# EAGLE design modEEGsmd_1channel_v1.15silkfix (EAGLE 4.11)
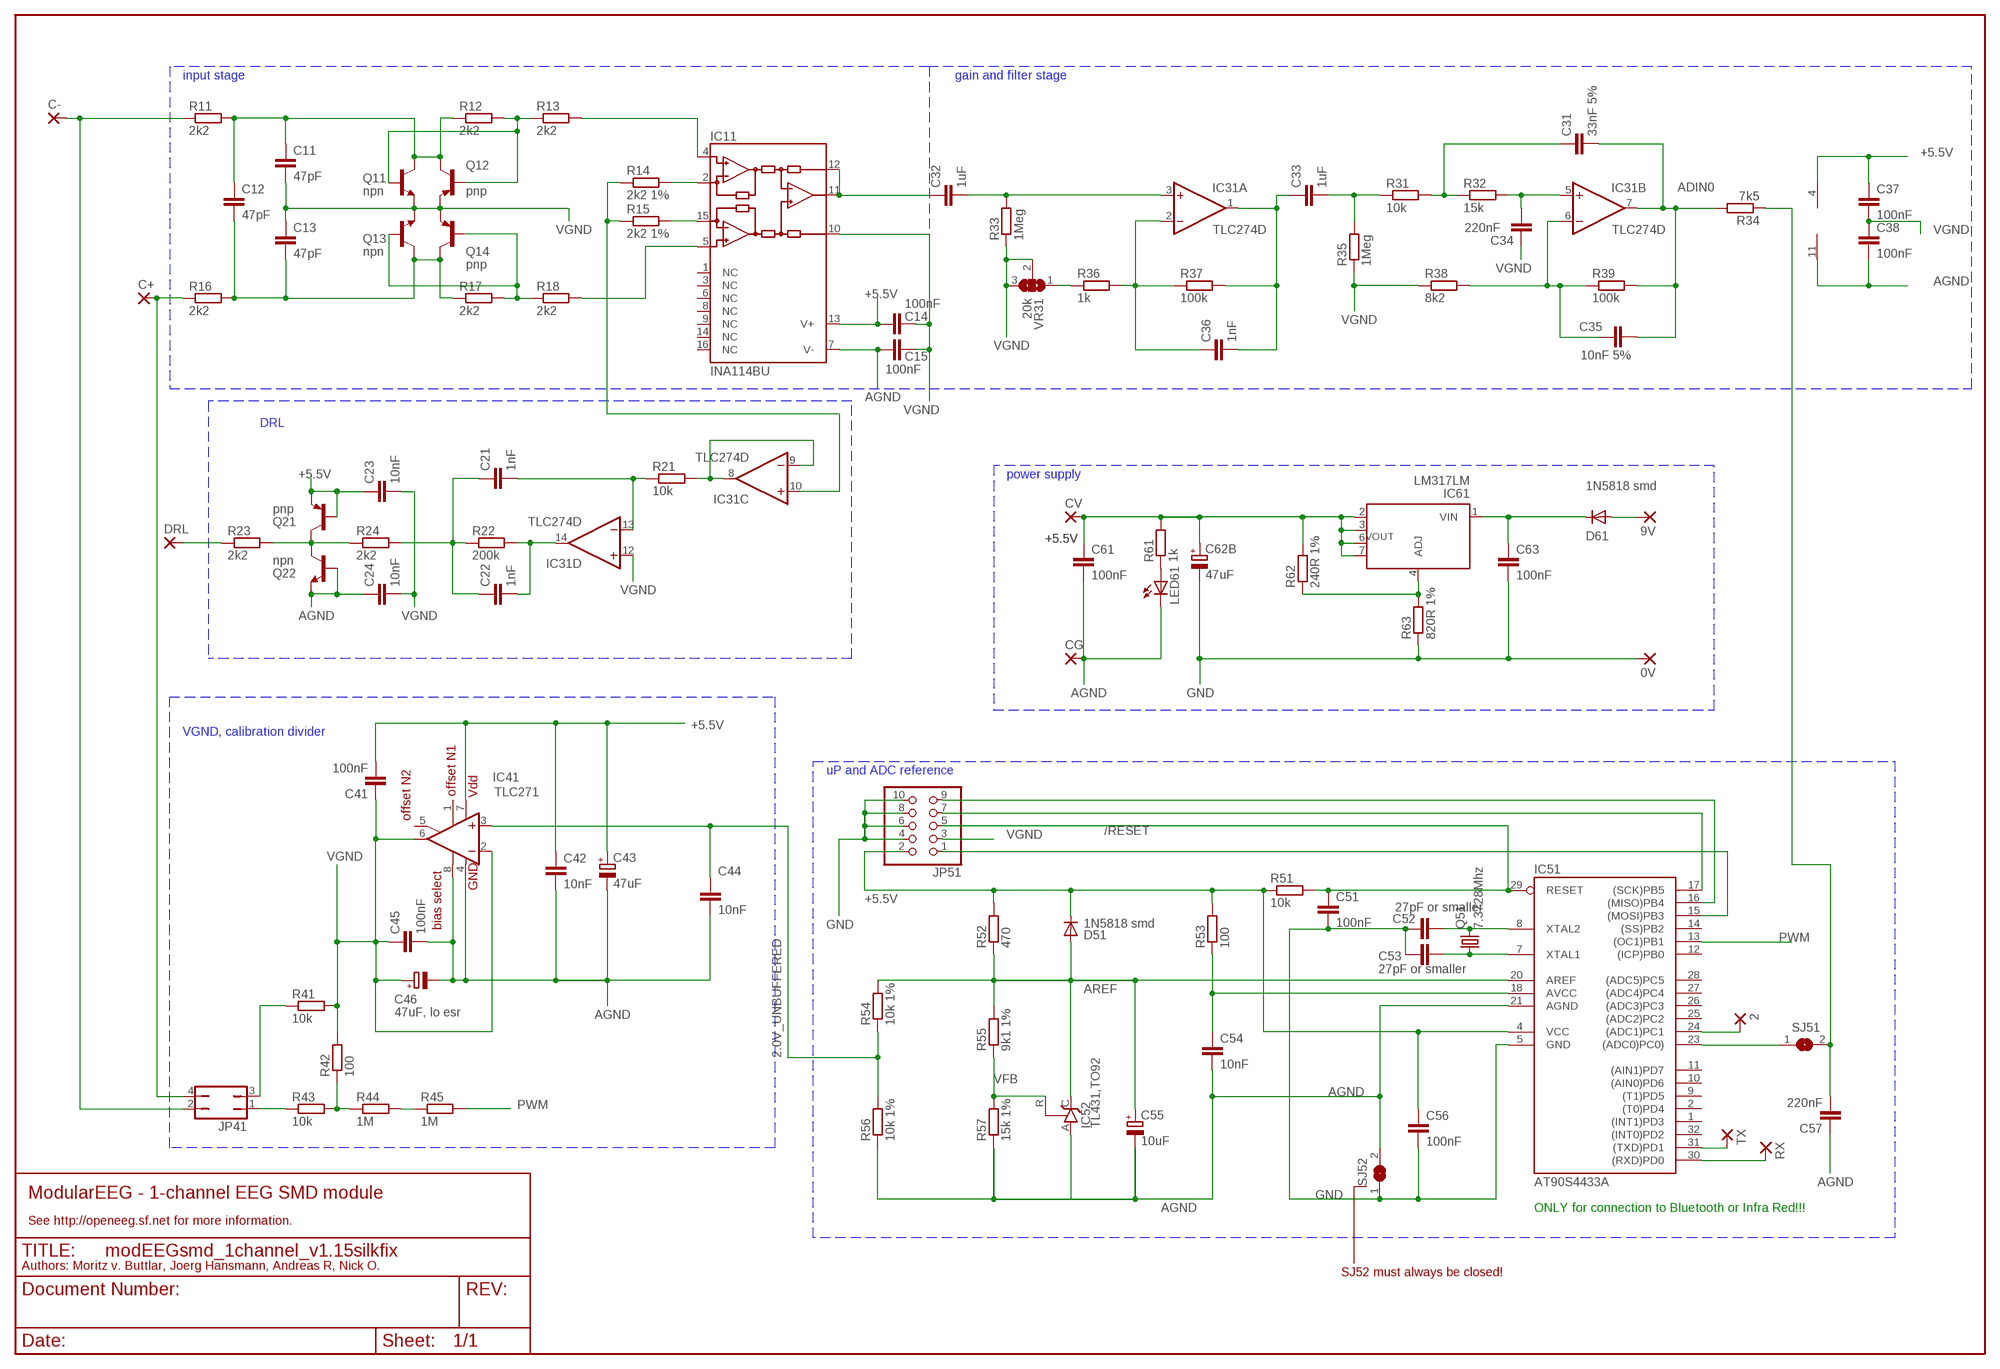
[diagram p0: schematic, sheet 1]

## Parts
0V  1,6/0,8  [1,6/0,8]
2  1,6/0,8  [1,6/0,8]
9V  1,6/0,8  [1,6/0,8]
C11  47pF  C-EUC0603K  [C0603K]
C12  47pF  C-EUC0603K  [C0603K]
C13  47pF  C-EUC0603K  [C0603K]
C14  100nF  C-EUC0603K  [C0603K]
C15  100nF  C-EUC0603K  [C0603K]
C21  1nF  C-EUC0603K  [C0603K]
C22  1nF  C-EUC0603K  [C0603K]
C23  10nF  C-EUC0603K  [C0603K]
C24  10nF  C-EUC0603K  [C0603K]
C31  33nF 5%  C-EUC1206K  [C1206K]
C32  1uF  C-EUC1210K  [C1210K]
C33  1uF  C-EUC1210K  [C1210K]
C34  220nF  C-EU  [C2416]
C35  10nF 5%  C-EUC0805K  [C0805K]
C36  1nF  C-EUC0603K  [C0603K]
C37  100nF  C-EUC0603K  [C0603K]
C38  100nF  C-EUC0603K  [C0603K]
C41  100nF  C-EUC0603K  [C0603K]
C42  10nF  C-EUC0603K  [C0603K]
C43  47uF  CPOL-EUCT3528  [CT3528]
C44  10nF  C-EUC0603K  [C0603K]
C45  100nF  C-EUC0603K  [C0603K]
C46  47uF, lo esr  CPOL-EUCT3528  [CT3528]
C51  100nF  C-EUC0603K  [C0603K]
C52  27pF or smaller  C-EUC0603K  [C0603K]
C53  27pF or smaller  C-EUC0603K  [C0603K]
C54  10nF  C-EUC0603K  [C0603K]
C55  10uF  CPOL-EUCT3216  [CT3216]
C56  100nF  C-EUC0603K  [C0603K]
C57  220nF  C-EU  [C2416]
C61  100nF  C-EUC0603K  [C0603K]
C62B  47uF  CPOL-EUCT3528  [CT3528]
C63  100nF  C-EUC0603K  [C0603K]
C+  1,6/0,8  [1,6/0,8]
C-  1,6/0,8  [1,6/0,8]
CG  1,6/0,8  [1,6/0,8]
CV  1,6/0,8  [1,6/0,8]
D51  1N5818 smd  DIODE-SMB  [SMB]
D61  1N5818 smd  DIODE-SMB  [SMB]
DRL  1,6/0,8  [1,6/0,8]
IC11  INA114BU  INA111U  [SO16-1]
IC31  TLC274D  [SO14]
IC41  TLC271  TLC271D  [SO08]
IC51  AT90S4433A  [TQFP32-08]
IC52  TL431,TO92  TL431CLP  [TO92-CLP]
IC61  LM317LM  [SO08]
JP41  JP2Q  [JP2Q]
JP51  PINHD-2X5  [2X05]
LED61  LEDCHIPLED_0805  [CHIPLED_0805]
Q11  npn  BC847SMD  [SOT23]
Q12  pnp  BC857CSMD  [SOT23-BEC]
Q13  npn  BC847SMD  [SOT23]
Q14  pnp  BC857CSMD  [SOT23-BEC]
Q21  pnp  BC857CSMD  [SOT23-BEC]
Q22  npn  BC847SMD  [SOT23]
Q51  7.3728Mhz  CRYTALHC49S  [HC49/S]
R11  2k2  R-EU_R0805  [R0805]
R12  2k2  R-EU_R0805  [R0805]
R13  2k2  R-EU_R0805  [R0805]
R14  2k2 1%  R-EU_R0805  [R0805]
R15  2k2 1%  R-EU_R0805  [R0805]
R16  2k2  R-EU_R0805  [R0805]
R17  2k2  R-EU_R0805  [R0805]
R18  2k2  R-EU_R0805  [R0805]
R21  10k  R-EU_R0805  [R0805]
R22  200k  R-EU_M0805  [M0805]
R23  2k2  R-EU_R0805  [R0805]
R24  2k2  R-EU_R0805  [R0805]
R31  10k  R-EU_R0805  [R0805]
R32  15k  R-EU_R0805  [R0805]
R33  1Meg  R-EU_R0805  [R0805]
R34  7k5  R-EU_R0805  [R0805]
R35  1Meg  R-EU_R0805  [R0805]
R36  1k  R-EU_R0805  [R0805]
R37  100k  R-EU_R0805  [R0805]
R38  8k2  R-EU_R0805  [R0805]
R39  100k  R-EU_R0805  [R0805]
R41  10k  R-EU_R0805  [R0805]
R42  100  R-EU_R0805  [R0805]
R43  10k  R-EU_R0805  [R0805]
R44  1M  R-EU_R0805  [R0805]
R45  1M  R-EU_R0805  [R0805]
R51  10k  R-EU_R0805  [R0805]
R52  470  R-EU_R0805  [R0805]
R53  100  R-EU_R0805  [R0805]
R54  10k 1%  R-EU_R0805  [R0805]
R55  9k1 1%  R-EU_R0805  [R0805]
R56  10k 1%  R-EU_R0805  [R0805]
R57  15k 1%  R-EU_R0805  [R0805]
R61  1k  R-EU_R0805  [R0805]
R62  240R 1%  R-EU_R0805  [R0805]
R63  820R 1%  R-EU_R0805  [R0805]
RX  1,6/0,8  [1,6/0,8]
SJ51  SJ  [SJ]
SJ52  SJ  [SJ]
TX  1,6/0,8  [1,6/0,8]
VR31  20k  SJ2W  [SJ_2]

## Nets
2.0V_UNBUFFERED: C44.1 IC41.3(+IN) R54.1 R56.2
+5.5V: C14.1 C23.1 C37.1 C41.2 C42.1 C43.+ C56.1 C61.1 C62B.+ CV.1(P) D51.C IC11.13(V+) IC31.4(P:V+) IC41.7(V+) IC51.4(VCC) IC61.2(VOUT) IC61.3(VOUT) IC61.6(VOUT) IC61.7(VOUT) JP51.2 Q21.B Q21.E R51.1 R52.2 R53.2 R61.2 R62.2
/RESET: C51.1 IC51.29(RESET) JP51.5 R51.2
ADC0: IC51.23((ADC0)PC0)) SJ51.1
ADC1: 2.1(P) IC51.24((ADC1)PC1)
ADIN0: C31.2 C35.2 IC31.7(B:OUT) R34.2 R39.2
AGND: C15.1 C24.1 C38.2 C42.2 C43.- C44.2 C45.2 C46.- C54.2 C55.- C57.1 C61.2 CG.1(P) IC11.7(V-) IC31.11(P:V-) IC41.4(V-) IC41.8(OPT) IC51.21(AGND) IC52.A LED61.C Q22.1(B) Q22.2(E) R56.1 R57.1 SJ52.2
AREF: C55.+ D51.A IC51.20(AREF) IC52.C R52.1 R54.2 R55.2
AVCC: C54.1 IC51.18(AVCC) R53.1
DRL: DRL.1(P) R23.1
GND: 0V.1(P) C51.2 C52.1 C53.1 C56.2 C62B.- C63.2 IC51.5(GND) JP51.4 JP51.6 JP51.8 JP51.10 R63.1 SJ52.1
N$1: IC11.2(RG) R14.2
N$2: IC11.15(RG) R15.2
N$3: IC31.10(C:+IN) R14.1 R15.1
N$4: C32.1 IC11.11(OUT) IC11.12(FB)
N$5: IC11.4(-IN) R13.2
N$6: R36.1 VR31.1
N$7: IC11.5(+IN) R18.2
N$8: C57.2 R34.1 SJ51.2
N$9: C11.1 C12.1 Q11.3(C) Q12.C R11.2 R12.1
N$10: Q13.1(B) Q14.B R17.2 R18.1
N$11: R44.2 R45.1
N$12: C52.2 IC51.8(XTAL2) Q51.2
N$13: C12.2 C13.2 Q13.3(C) Q14.C R16.2 R17.1
N$14: Q11.1(B) Q12.B R12.2 R13.1
N$15: C-.1(P) JP41.2 R11.1
N$16: C+.1(P) JP41.4 R16.1
N$17: C32.2 IC31.3(A:+IN) R33.2
N$18: C36.1 IC31.2(A:-IN) R36.2 R37.1
N$19: C53.2 IC51.7(XTAL1) Q51.1
N$20: Q21.C Q22.3(C) R23.2 R24.1
N$22: C33.1 C36.2 IC31.1(A:OUT) R37.2
N$23: C33.2 R31.1 R35.2
N$24: C35.1 IC31.6(B:-IN) R38.2 R39.1
N$25: IC61.4(ADJ) R62.1 R63.2
N$27: IC51.17((SCK)PB5) JP51.7
N$30: JP41.3 R41.1
N$33: C22.2 IC31.14(D:OUT) R22.2
N$34: R42.1 R43.2 R44.1
N$38: C63.1 D61.C IC61.1(VIN)
N$39: LED61.A R61.1
N$40: 9V.1(P) D61.A
N$41: C21.2 IC31.13(D:-IN) R21.1
N$42: IC51.16((MISO)PB4) JP51.9
N$43: IC51.15((MOSI)PB3) JP51.1
N$45: IC31.8(C:OUT) IC31.9(C:-IN) R21.2
N$48: JP41.1 R43.1
N$53: C31.1 R31.2 R32.1
N$54: C34.2 IC31.5(B:+IN) R32.2
PWM: IC51.13((OC1)PB1) R45.2
RLEG: C21.1 C22.1 R22.1 R24.2
RX: IC51.30((RXD)PD0) RX.1(P)
TX: IC51.31((TXD)PD1) TX.1(P)
VFB: IC52.R R55.1 R57.2
VGND: C11.2 C13.1 C14.2 C15.2 C23.2 C24.2 C34.1 C37.2 C38.1 C41.1 C45.1 C46.+ IC11.10(REF) IC31.12(D:+IN) IC41.2(-IN) IC41.6(OUT) JP51.3 Q11.2(E) Q12.E Q13.2(E) Q14.E R33.1 R35.1 R38.1 R41.2 R42.2 VR31.2 VR31.3
Unconnected: IC11.1(NC) IC11.3(NC) IC11.6(NC) IC11.8(NC) IC11.9(NC) IC11.14(NC) IC11.16(NC) IC41.1(ON1) IC41.5(ON2) IC51.1((INT1)PD3) IC51.2((T0)PD4) IC51.9((T1)PD5) IC51.10((AIN0)PD6) IC51.11((AIN1)PD7) IC51.12((ICP)PB0) IC51.14((SS)PB2) IC51.25((ADC2)PC2) IC51.26((ADC3)PC3) IC51.27((ADC4)PC4) IC51.28((ADC5)PC5) IC51.32((INT0)PD2)

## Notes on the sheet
- input stage | gain and filter stage
- DRL
- power supply
- VGND, calibration divider
- uP and ADC reference
- offset N1 | Vdd
- offset N2
- GND
- bias select
- ModularEEG - 1-channel EEG SMD module
- ONLY for connection to Bluetooth or Infra Red!!!
- See http://openeeg.sf.net for more information.
- Authors: Moritz v. Buttlar, Joerg Hansmann, Andreas R, Nick O.
- SJ52 must always be closed!

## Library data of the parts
0V 2 9V C+ C- CG CV DRL RX TX = WIREPAD:1,6/0,8: THROUGH-HOLE PAD
C11-C15 C21-C24 C31-C38 C41 C42 C44 C45 C51-C54 C56 C57 C61 C63 = rcl:C-EU: CAPACITOR, European symbol
C43 C46 C55 C62B = rcl:CPOL-EU: POLARIZED CAPACITOR, European symbol
D51 D61 = diode:DIODE-: DIODE
IC11 = burr-brown:INA111U: Precision Instrumentation Amplifier
IC31 = linear:TLC274: OP AMP
IC41 = linear:TLC271: OP AMP
IC51 = atmel:AT90S4433: MICROCONTROLLER 4 Kbytes FLASH 128 bytes SRAM 256 bytes EEPROM UART 6-channel 10 bit ADC
IC52 = v-reg:TL431CLP: VOLTAGE REGULATOR
IC61 = linear:LM317LM
JP41 = jumper:JP2Q: JUMPER
JP51 = pinhead:PINHD-2X5: PIN HEADER
LED61 = led:LED: LED
Q11 Q13 Q22 = transistor-npn:BC847*: NPN Transistor
Q12 Q14 Q21 = transistor-pnp:BC857*: PNP Transistror
Q51 = crystal:CRYTAL: CRYSTAL
R11-R18 R21-R24 R31-R39 R41-R45 R51-R57 R61-R63 = rcl:R-EU_: RESISTOR, European symbol
SJ51 SJ52 = jumper:SJ: SMD solder JUMPER
VR31 = jumper:SJ2W: SMD solder JUMPER

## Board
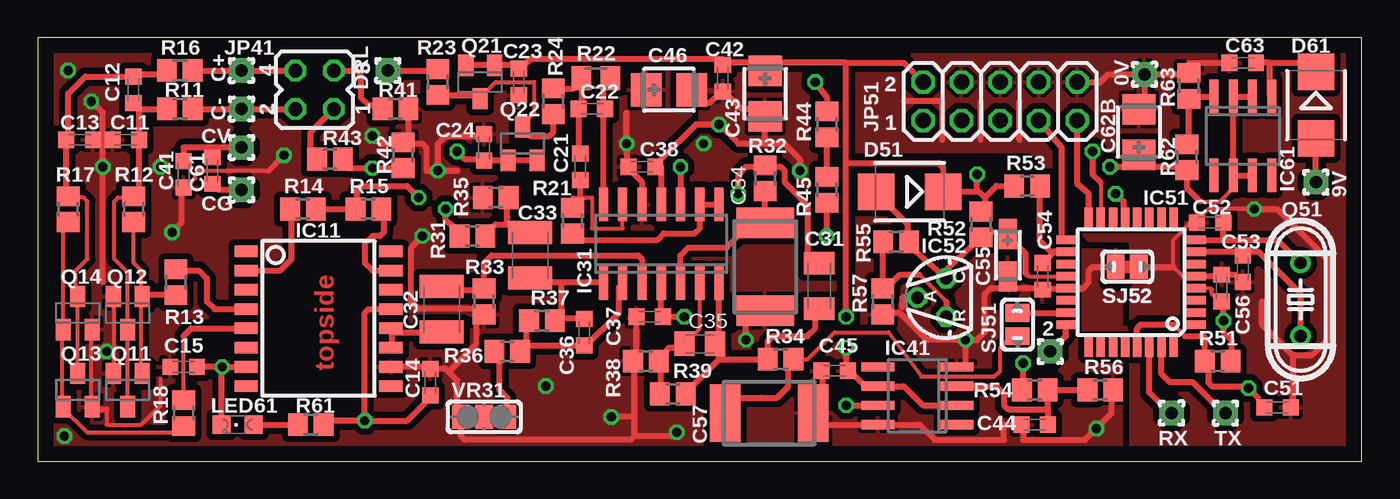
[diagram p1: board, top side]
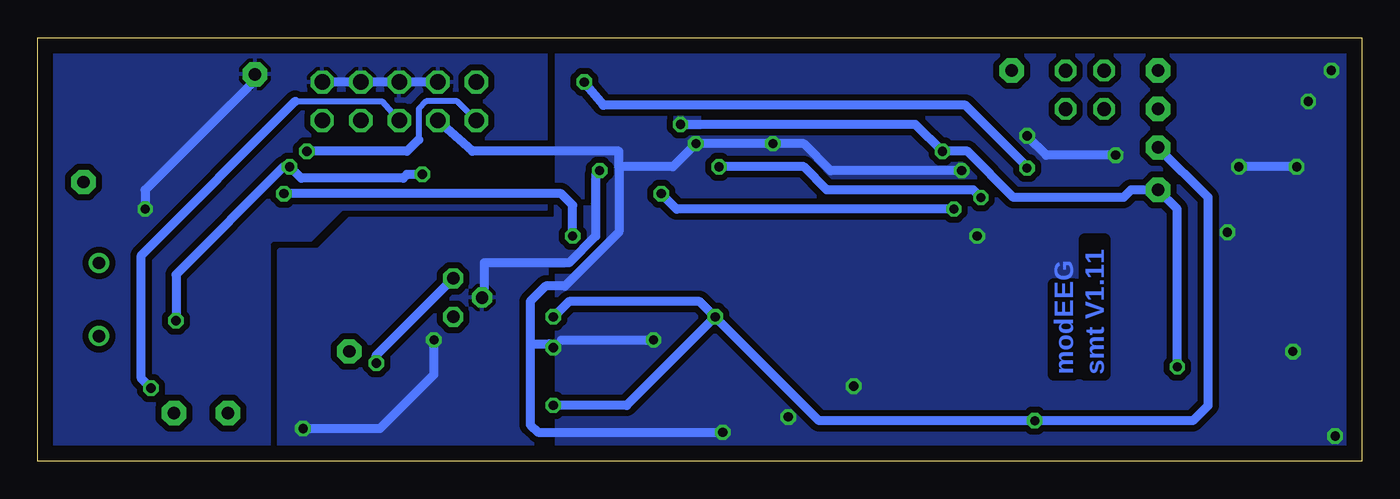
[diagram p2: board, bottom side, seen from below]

Size 87.3 x 27.93 mm. Coordinates in mm from the lower left corner, seen from the top.
Outline: 0,0 87.3,0 87.3,27.93 0,27.93 0,0
Copper layers (1*16): Top 0.035mm / dielectric 1.5mm / Bottom 0.035mm
Design rules "OLIMEX_8mils": minimum track width 10mil, minimum drill 24mil, track to track 8mil, track to pad 8mil, pad to pad 8mil, via to via 8mil, smd to smd 8mil, copper to edge 40mil, drill to drill 10mil, minimum pad ring 10mil, minimum via ring 8mil, stop-mask expansion 0mil, vias tented up to drill 0mil, thermal gap 10mil
tRestrict: 6 lines

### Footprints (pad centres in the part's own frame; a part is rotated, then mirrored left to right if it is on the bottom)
1,6/0,8 = drill 0.813 pad 1.6 octagon: 1 0,0
C0603K = smd 1.05 x 1.08: 1 -0.875,0; 2 0.875,0
C1206K = smd 1.5 x 2: 1 -1.5,0; 2 1.5,0
C1210K = smd 1.5 x 2.9: 1 -1.5,0; 2 1.5,0
C2416 = smd 2 x 3.8: 1 -2.9,0; 2 2.9,0
C0805K = smd 1.3 x 1.6: 1 -1,0; 2 1,0
CT3528 = smd 2 x 2.2: + 1.5,0; - -1.5,0
CT3216 = smd 2 x 1.2: + 1.4,0; - -1.4,0
SMB = smd 2.4 x 2.4: A 2.2,0; C -2.2,0
SO16-1 = smd 0.762 x 1.524: 1 -4.445,-4.775; 2 -3.175,-4.775; 3 -1.905,-4.775; 4 -0.635,-4.775; 5 0.635,-4.775; 6 1.905,-4.775; 7 3.175,-4.775; 8 4.445,-4.775; 9 4.445,4.775; 10 3.175,4.775; 11 1.905,4.775; 12 0.635,4.775; 13 -0.635,4.775; 14 -1.905,4.775; 15 -3.175,4.775; 16 -4.445,4.775
SO14 = smd 0.6 x 2.2: 1 -3.81,-2.6; 2 -2.54,-2.6; 3 -1.27,-2.6; 4 0,-2.6; 5 1.27,-2.6; 6 2.54,-2.6; 7 3.81,-2.6; 8 3.81,2.6; 9 2.54,2.6; 10 1.27,2.6; 11 0,2.6; 12 -1.27,2.6; 13 -2.54,2.6; 14 -3.81,2.6
SO08 = smd 0.6 x 2.2: 1 -1.905,-2.6; 2 -0.635,-2.6; 3 0.635,-2.6; 4 1.905,-2.6; 5 1.905,2.6; 6 0.635,2.6; 7 -0.635,2.6; 8 -1.905,2.6
TQFP32-08 = smd 1.27 x 0.559: 1 -4.293,2.8; 2 -4.293,2; 3 -4.293,1.2; 4 -4.293,0.4; 5 -4.293,-0.4; 6 -4.293,-1.2; 7 -4.293,-2; 8 -4.293,-2.8; 17 4.293,-2.8; 18 4.293,-2; 19 4.293,-1.2; 20 4.293,-0.4; 21 4.293,0.4; 22 4.293,1.2; 23 4.293,2; 24 4.293,2.8 | smd 0.559 x 1.27: 9 -2.8,-4.293; 10 -2,-4.293; 11 -1.2,-4.293; 12 -0.4,-4.293; 13 0.4,-4.293; 14 1.2,-4.293; 15 2,-4.293; 16 2.8,-4.293; 25 2.8,4.293; 26 2,4.293; 27 1.2,4.293; 28 0.4,4.293; 29 -0.4,4.293; 30 -1.2,4.293; 31 -2,4.293; 32 -2.8,4.293
TO92-CLP = drill 0.813 octagon: A 0,1.905; C 1.27,0; R -1.27,0
JP2Q = drill 0.914 pad 1.422 octagon: 1 -1.27,-1.27; 2 -1.27,1.27; 3 1.27,-1.27; 4 1.27,1.27
2X05 = drill 1.016 pad 1.524 octagon: 1 -5.08,-1.27; 2 -5.08,1.27; 3 -2.54,-1.27; 4 -2.54,1.27; 5 0,-1.27; 6 0,1.27; 7 2.54,-1.27; 8 2.54,1.27; 9 5.08,-1.27; 10 5.08,1.27
CHIPLED_0805 = smd 1.2 x 1.2: A 0,-1.05; C 0,1.05
SOT23 = smd 1 x 1.4: 1 -0.95,-1.1; 2 0.95,-1.1; 3 0,1.1
SOT23-BEC = smd 1 x 1.4: B -0.95,-1.1; C 0,1.1; E 0.95,-1.1
HC49/S = drill 0.813 round: 1 -2.413,0; 2 2.413,0
R0805 = smd 1.3 x 1.5: 1 -0.85,0; 2 0.85,0
M0805 = smd 1.3 x 1.6: 1 -0.95,0; 2 0.95,0
SJ = smd 1.168 x 1.6: 1 -0.762,0; 2 0.762,0
SJ_2 = smd 1.168 x 1.6: 1 -1.524,0; 2 0,0; 3 1.524,0

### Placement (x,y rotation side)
0V  72.99,25.52 270 top
2  66.76,7.23 90 top
9V  84.29,18.41 270 top
C11  5.8,21.2 180 top
C12  6.31,24.51 90 top
C13  2.76,21.2 180 top
C14  25.87,5.2 90 top
C15  9.61,6.22 180 top
C21  35.78,19.43 270 top
C22  36.54,23.24 0 top
C23  31.71,25.01 270 top
C24  29.43,20.7 90 top
C31  51.52,11.55 270 top
C32  26.63,10.03 90 top
C33  32.47,13.58 90 top
C34  47.97,12.82 90 top
C35  43.65,7.74 0 top
C36  36.03,8.5 90 top
C37  40.35,9.52 180 top
C38  39.84,19.43 0 top
C41  9.61,18.92 90 top
C42  45.17,25.27 270 top
C43  47.97,24.25 90 top
C44  65.75,2.41 180 top
C45  52.54,5.96 180 top
C46  41.62,24.51 180 top
C51  81.75,3.55 0 top
C52  77.31,15.74 0 top
C53  79.46,12.7 90 top
C54  66.26,12.19 270 top
C55  63.97,13.58 90 top
C56  78.07,11.43 90 top
C57  48.22,3.17 180 top
C61  11.52,19.17 270 top
C62B  72.61,21.71 270 top
C63  79.46,26.28 180 top
C+  13.42,25.78 90 top
C-  13.42,23.24 90 top
CG  13.42,17.9 90 top
CV  13.42,20.7 90 top
D51  57.49,17.77 180 top
D61  84.29,23.49 270 top
DRL  23.08,25.78 90 top
IC11  18.5,9.39 270 top
IC31  41.11,14.35 0 top
IC41  58,4.31 90 top
IC51  72.1,11.81 180 top
IC52  59.91,10.79 90 top
IC61  79.46,21.46 180 top
JP41  18.25,24.51 90 top
JP51  63.46,23.74 0 top
LED61  13.17,2.41 90 top
Q11  5.93,4.69 180 top
Q12  5.93,9.77 180 top
Q13  2.63,4.69 0 top
Q14  2.63,9.77 0 top
Q21  29.17,25.01 180 top
Q22  31.97,20.95 0 top
Q51  83.27,10.66 90 top
R11  9.36,23.24 180 top
R12  6.31,16.63 270 top
R13  9.11,11.81 90 top
R14  17.49,16.63 180 top
R15  21.81,16.63 0 top
R16  9.36,25.78 180 top
R17  1.99,16.63 270 top
R18  9.61,3.17 90 top
R21  35.27,15.87 270 top
R22  36.79,25.27 0 top
R23  26.38,25.01 270 top
R24  34,23.74 90 top
R31  28.66,14.85 180 top
R32  47.97,18.66 270 top
R33  29.43,10.54 90 top
R34  48.98,6.73 180 top
R35  30.19,17.39 0 top
R36  30.95,7.23 0 top
R37  33.24,9.27 0 top
R38  40.09,6.6 0 top
R39  41.87,4.44 0 top
R41  23.58,23.24 0 top
R42  24.09,20.19 90 top
R43  19.27,19.93 0 top
R44  52.03,22.22 270 top
R45  52.03,17.9 270 top
R51  77.81,6.6 180 top
R52  62.19,15.62 90 top
R53  65.24,18.16 180 top
R54  65.75,4.69 180 top
R55  56.6,14.47 0 top
R56  70.07,4.69 180 top
R57  55.72,10.54 90 top
R61  18,2.41 0 top
R62  75.78,20.06 270 top
R63  75.91,24.76 270 top
RX  74.77,3.17 270 top
SJ51  64.61,9.01 270 top
SJ52  71.84,12.82 180 top
TX  78.32,3.17 180 top
VR31  29.43,2.92 180 top

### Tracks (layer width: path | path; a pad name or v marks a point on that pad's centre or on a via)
2.0V_UNBUFFERED
  Top 0.254: C44.1 66.62,2.55 66.51,2.66 66.6,2.75
  Top 0.406: 66.6,3.42 66.6,2.75 | 66.6,3.42 R54.1 R56.2 | IC41.3 63.21,4.95 63.72,4.44 63.72,3.68 63.97,3.42 66.6,3.42
+5.5V  (via drill 0.61)
  Top 0.254: 41.11,9.63 C37.1 41.11,9.52 | 47.97,26.28 C43.+ | 45.17,26.28 45.17,26.26 45.2,26.26 45.17,26.28 | R61.2 19.01,2.41 19.27,2.66 | 25.87,4.19 C14.1 | IC51.4 77.32,11.41 77.43,11.3 77.43,11.04 77.94,10.54 77.95,10.55 C56.1 78.18,10.55 78.19,10.54 | 72.86,19.55 72.86,19.43 72.61,19.68 C62B.+ | IC61.3 78.9,24.06 78.96,24 79.02,24.06 | 78.83,19.04 78.96,18.92 78.9,18.86 IC61.6 78.76,18.86 78.7,18.92 78.7,17.9 77.94,17.14 76.67,17.14 | IC61.7 80.03,18.86 79.97,18.92 79.91,18.86 | R62.2 75.69,19.21 75.65,19.17 75.4,19.43 | 62.45,16.89 R52.2 | 61.94,17.77 62.07,17.77 | 78.7,6.73 78.66,6.69 R51.1 | R53.2 64.48,18.16 | C61.1 11.39,20.17 11.39,20.44 11.14,20.7 | 30.12,26.1 30.19,26.03 | Q21.B 30.12,26.1 | 30.12,26.1 30.1,26.11 | C23.1 31.71,25.78 31.63,25.86 | 31.82,25.89 C23.1 | 45.17,26.28 C42.1 | 45.17,26.28 45.17,26.54 | C23.1 31.71,26.03 31.63,26.11
  Top 0.406: 41.11,9.63 IC31.4 | 45.17,26.28 47.97,26.28 53.3,26.28 | v21.55,2.66 19.27,2.66 | v21.55,2.66 24.35,2.66 25.87,4.19 | IC11.13 21.81,10.03 21.55,9.77 v21.55,2.66 | v42.63,9.52 C37.1 | v70.7,19.43 72.86,19.43 75.4,19.43 | 79.02,24.06 IC61.2 | 78.83,19.04 IC61.3 | IC61.6 79.91,18.86 | R62.2 75.78,18.03 76.67,17.14 | 53.3,26.28 57.11,26.28 JP51.2 | 62.07,17.77 62.45,17.39 | 62.45,17.39 62.45,16.89 | 78.19,10.54 v78.19,9.27 78.19,8.5 78.7,8 78.7,6.73 | v53.3,3.68 IC41.7 | v53.3,9.52 53.3,19.68 | 53.3,19.68 53.3,26.28 | 62.45,17.39 63.21,18.16 R53.2 | v61.94,18.92 61.94,17.77 D51.C 59.69,19.38 59.4,19.68 53.3,19.68 | CV.1 11.14,20.7 9.61,20.7 C41.2 | 30.1,26.11 Q21.E | 31.82,25.89 32.47,26.54 45.17,26.54 | 31.63,26.11 Q21.B
  Bottom 0.61: CV.1 10.12,17.39 10.12,3.68 11.14,2.66 v21.55,2.66 35.78,2.66 v42.63,9.52 | v78.19,9.27 78.19,12.31 71.08,19.43 v70.7,19.43 69.94,18.66 63.21,18.66 62.95,18.92 v61.94,18.92 | v42.63,9.52 48.48,3.68 v53.3,3.68 | v42.63,9.52 43.65,10.54 52.29,10.54 v53.3,9.52
/RESET  (via drill 0.61)
  Top 0.254: IC51.29 72.5,7.49 72.48,7.49 | 72.73,9.01 72.75,9.01 | 76.96,6.69 R51.2 77.18,6.38 | 74.89,9.01 75.65,8.25 | C51.1 80.75,3.42 80.48,3.42 80.48,4.19 | 79.72,4.95 v79.84,4.82
  Top 0.406: IC51.29 72.48,8.76 72.73,9.01 | 72.75,9.01 74.89,9.01 | 77.18,6.38 77.18,5.2 77.43,4.95 79.72,4.95 | v79.84,4.82 80.48,4.19 | R51.2 76.92,6.6 76.92,8.25 75.65,8.25
  Bottom 0.406: JP51.5 64.61,23.74 70.32,23.74
  Bottom 0.61: 70.32,23.74 80.48,13.58 80.48,5.46 v79.84,4.82
ADC0
  Top 0.254: 67.78,9.77 IC51.23
  Top 0.406: SJ51.1 67.78,9.77
ADC1
  Top 0.406: IC51.24 67.81,8.28 2.1
ADIN0
  Top 0.254: 42.38,4.02 R39.2 42.63,4.44 | R34.2 48.22,6.73 | 44.41,7.74 C35.2 44.92,7.74
  Top 0.406: IC31.7 44.92,7.74 44.92,6.73 | 42.63,4.44 44.92,6.73 | 44.92,6.73 45.17,6.73 | 45.17,6.73 R34.2 48.13,7.91 48.48,8.25 50.76,8.25 51.27,8.76 51.27,10.03 51.29,10.05 C31.2 | 45.17,6.73 45.17,7.23
AGND  (via drill 0.61)
  Top 0.254: 55.8,9.77 R57.1 | C15.1 10.38,6.22 | 45.29,24.39 C42.2 45.17,24.51 | IC41.4 61.18,6.22 61.43,6.22 | 11.91,17.9 C61.2 | 12.12,6.18 v12.15,6.22 | 51.78,5.96 C45.2 | 51.78,2.41 51.78,3.17 C57.1 | 70.83,4.69 R56.1 | 66.13,11.43 C54.2 | C54.2 | C54.2 66.36,11.41 | 62.83,11.43 63.84,11.43 63.97,11.55 C55.- 63.97,12.31 | C46.- 43.14,24.51 44.02,23.63 | 41.11,19.93 41.11,19.43 C38.2 40.6,19.43 | 31.02,19.87 30.95,19.93 | Q22.1 31.02,19.87 | 31.02,19.87 31.03,19.85 | C24.1 29.43,19.93 29.51,19.85 | C43.- 47.97,23.24 47.97,22.73 C43.-
  Top 0.406: v61.18,8 58.64,8 56.86,9.77 55.8,9.77 | C15.1 v12.15,6.22 IC11.7 | 47.97,20.95 47.97,22.73 | 45.29,24.39 46.44,23.24 47.97,23.24 | 47.97,20.95 46.19,20.95 v44.92,22.22 43.4,22.22 41.11,19.93 | 70.83,4.69 70.83,3.17 v69.81,2.15 69.05,1.39 64.99,1.39 64.99,2.41 C44.2 63.72,2.41 63.72,1.39 59.14,1.39 58.13,2.41 IC41.8 51.78,2.41 | v61.18,8 61.18,6.22 | CG.1 11.91,17.9 | LED61.C 12.12,6.18 | 51.78,3.17 51.78,5.96 | 66.13,11.43 62.83,11.43 62.45,11.04 62.45,8.5 61.94,8 v61.18,8 | 66.36,11.41 IC51.21 68.9,11.41 69.3,11.81 69.3,12.57 69.56,12.82 SJ52.2 | v50.25,19.17 50.25,19.93 49.24,20.95 47.97,20.95 | 41.11,19.43 IC31.11 | 31.03,19.85 Q22.2 | 29.51,19.85 Q22.1 | 29.43,19.93 28.16,19.93 v27.65,20.44 | 44.02,23.63 44.3,23.63 45.17,24.51 | IC52.A 56.99,10.79 56.99,10.16
  Bottom 0.254: v50.25,19.17 50.51,18.92
  Bottom 0.61: v44.92,22.22 29.43,22.22 v27.65,20.44 26,20.44 22.95,17.39 15.71,17.39 15.2,17.9 CG.1 12.15,16.63 v12.15,6.22 | v69.81,2.15 64.73,2.15 61.18,5.71 v61.18,8 | 50.51,18.92 50.51,14.85 52.29,13.08 57.87,13.08 57.87,10.79 IC52.A
  pour Top (isolate 0.406, rank 2): 43.65,35.68 75.65,35.68 75.65,-6.23 43.65,-6.23
  pour Bottom (isolate 0.406, rank 2): 43.65,35.68 75.65,35.68 75.65,-6.23 43.65,-6.23
AREF  (via drill 0.61)
  Top 0.254: IC51.20 67.81,12.19 65.37,12.19 65.24,12.31 | 55.29,17.69 D51.A | 57.37,14.56 R55.2 57.58,14.35 57.62,14.35 57.62,14.09 | R52.1 62.45,15.11 | R54.2 64.99,4.69 | 63.97,15.11 C55.+
  Top 0.406: 55.29,17.69 57.37,15.62 57.37,14.56 | R52.1 59.91,12.61 IC52.C 57.62,14.09 | 62.45,15.11 63.97,15.11 63.97,14.85 65.11,13.71 65.11,12.44 65.24,12.31 | 64.99,4.69 v64.99,6.47
  Bottom 0.61: v64.99,6.47 64.99,6.98 IC52.C
AVCC
  Top 0.254: R53.1 66,18.16 | 66.26,13.08 C54.1
  Top 0.406: 66.89,13.71 67.02,13.84 67.78,13.84 IC51.18 | 66.89,13.71 66.26,13.08 | R53.1 66.09,14.51 66.89,13.71
DRL
  Top 0.254: 26.38,25.78 R23.1
  Top 0.406: DRL.1 26.38,25.78
GND  (via drill 0.61)
  Top 0.254: 78.18,12.3 78.19,12.31 | 78.18,12.3 C56.2 78.05,12.31 77.94,12.31 | 78.09,12.21 78.18,12.3 | 78.97,12.31 C53.1 79.46,11.81 | IC51.5 75.51,12.21 74.89,12.82 74.89,14.6 76.42,16.12 76.43,16.11 C52.1 | R63.1 75.91,25.52 | R63.1 75.91,26.28 | 75.82,25.52 R63.1 | v80.23,16.63 77.18,16.63 76.42,15.87 | 82.75,3.68 82.77,3.68 82.62,3.54 | 82.62,3.54 82.51,3.42 | 82.62,3.54 C51.2 | C62B.- 72.61,23.24 72.99,22.85 72.99,22.35
  Top 0.406: IC51.5 78.09,12.21 | 78.05,12.31 78.97,12.31 | SJ52.1 74.89,12.82 | 75.91,26.28 C63.2 | 0V.1 75.82,25.52 | 0V.1 70.57,25.52 70.33,25.28 70.08,25.01 JP51.10 | 0V.1 72.99,22.85 | 80.73,10.54 80.73,9.01 82.77,6.98 | 82.77,6.98 84.04,6.98 85.05,8 85.05,13.33 81.75,16.63 v80.23,16.63 | 82.77,6.98 82.77,3.68 | 57.11,23.74 59.65,23.74 59.65,21.2 | 62.19,21.2 62.19,23.74 | 64.73,21.2 64.73,23.74
  Top 0.813: 70.83,12.82 SJ52.1
  Bottom 0.254: 0V.1 72.99,25.14
  Bottom 0.61: 72.99,25.14 80.23,17.9 v80.23,16.63 | JP51.10 JP51.8 JP51.6 JP51.4
  pour Top (isolate 0.406): 53.81,32.63 53.81,20.44 65.49,20.44 68.03,17.9 68.03,15.87 69.3,14.6 71.84,14.6 72.1,14.35 72.1,-2.93 89.88,-2.93 89.88,32.63
  pour Bottom (isolate 0.406): 53.81,32.63 53.81,16.63 67.27,16.63 69.3,14.6 71.84,14.6 72.1,14.35 72.1,-2.93 89.88,-2.93 89.88,32.63
N$1
  Top 0.254: 16.73,16.63 R14.2
  Top 0.406: IC11.2 15.96,12.57 16.73,13.33 16.73,16.63
N$2
  Top 0.254: 22.57,16.63 R15.2 22.82,16.63
  Top 0.406: IC11.15 22.06,12.57 21.55,13.08 21.55,14.35 22.06,14.85 22.57,14.85 22.82,15.11 22.82,16.63
N$3  (via drill 0.61)
  Top 0.254: R14.1 18.25,16.63 | R15.1 21.04,16.72
  Top 0.406: R14.1 R15.1 | 21.04,16.72 21.04,17.9 21.3,18.16 24.35,18.16 v25.11,17.39 | v42.38,19.43 IC31.10
  Bottom 0.61: v42.38,19.43 36.79,19.43 35.27,17.9 25.62,17.9 v25.11,17.39
N$4
  Top 0.254: 23.33,8.76 IC11.12 23.53,8.5 | 23.33,7.54 IC11.11 | 26.35,8.5 C32.1
  Top 0.406: 23.33,8.76 23.33,7.54 | 23.53,8.5 26.35,8.5
N$5
  Top 0.254: R13.2 9.11,12.57
  Top 0.406: IC11.4 11.65,10.03 11.14,10.54 11.14,12.06 10.63,12.57 9.11,12.57
N$6
  Top 0.254: 30.44,6.89 R36.1
  Top 0.406: 30.44,6.89 30.44,4.69 30.95,4.19 VR31.1
N$7
  Top 0.254: R18.2 9.61,8.25
  Top 0.406: 9.61,8.25 10.12,8.76 IC11.5
N$8
  Top 0.254: 49.49,5.96 49.58,6.31 49.83,6.31 R34.1 50.76,6.73 52.54,8.5 56.1,8.5 58.26,5.58 63.08,5.58 63.46,5.96 63.46,7.49 64.22,8.25 SJ51.2 | C57.2 45.17,3.17 45.17,4.19
  Top 0.406: 49.49,5.96 49.49,4.95 48.73,4.19 47.71,4.19 45.17,4.19
N$9
  Top 0.254: 5.93,3.42 Q11.3 Q12.C 5.93,12.44 5.04,13.33 5.04,17.14 5.3,17.39 5.55,17.39 6.31,17.65 | 6.31,23.74 6.82,23.24 | 6.31,23.74 C12.1 | 6.68,23.38 6.31,23.74 | 6.31,17.65 6.68,18.01 | 6.31,17.65 R12.1
  Top 0.406: 6.82,23.24 R11.2 | 6.68,23.38 C11.1 6.68,18.01
N$10
  Top 0.254: R18.1 9.96,1.9 3.26,1.9 1.49,3.65 | 1.49,3.65 1.74,3.68 | 1.49,3.65 Q13.1 1.61,3.66 1.61,8.63 1.64,8.63 Q14.B 1.68,15.55 1.99,15.87 R17.2
N$11
  Top 0.254: R45.1 52.03,18.66
  Top 0.406: R45.1 R44.2
N$12
  Top 0.254: Q51.2 83.15,13.08 | IC51.8
  Top 0.406: 78.19,14.6 81.75,14.6 Q51.2 | 78.19,14.6 C52.2 | IC51.8 78.19,14.6
N$13
  Top 0.254: Q13.3 Q14.C 2.63,11.04 2.5,11.17 2.5,12.57 3.26,13.33 3.26,17.14 3.01,17.39 1.99,17.39 | C12.2 6.31,25.52 | 8.26,25.52 R16.2 | C13.2 1.99,21.2 | 1.99,17.39 1.88,17.51 | 2.25,17.65 2.08,17.48 R17.1 1.99,17.39
  Top 0.406: 6.31,25.52 8.26,25.52 | C12.2 3.12,25.38 1.99,24.25 1.99,21.2 | 1.88,17.51 C13.2
N$14
  Top 0.254: 6.82,5.73 6.82,5.71 | Q11.1 6.82,5.73 | 6.82,5.73 6.82,10.81 Q12.B 6.88,10.98 6.82,11.04 6.82,12.57 6.31,13.08 R12.2 6.31,15.87 | R13.1 9.11,11.04 9.04,10.98
  Top 0.406: 6.88,10.98 9.04,10.98
N$15
  Top 0.406: JP41.2 C-.1 R11.1
N$16
  Top 0.406: JP41.4 C+.1 R16.1
N$17
  Top 0.254: 29.43,11.3 R33.2 | C32.2 26.61,11.3
  Top 0.406: 26.61,11.3 29.43,11.3 | IC31.3 39.84,13.33 39.59,13.58 29.93,13.58 29.43,13.08 R33.2
N$18
  Top 0.254: 32.22,9.27 R37.1 32.47,9.27 32.22,9.01 | R36.2 32.22,7.65 32.22,7.74 32.33,7.63 | 38.32,11.49 IC31.2 | C36.1 36.03,7.49
  Top 0.406: 38.32,11.49 38.32,9.77 36.03,7.49 | 32.22,7.74 32.22,9.01 | 32.33,7.63 C36.1
N$19
  Top 0.254: C53.2 79.46,13.58 79.69,13.81
  Top 0.406: 80.51,13.81 IC51.7 | 80.51,13.81 83.27,11.04 Q51.1 | 80.51,13.81 79.69,13.81
N$20
  Top 0.254: 29.01,24.16 29.17,24 | 29.17,23.74 Q21.C 29.17,24 | 29.17,24 30.19,25.01 32.73,25.01 32.73,22.98 31.97,22.22 Q22.3 31.97,21.97 32.47,21.46 | R24.1 34,22.98
  Top 0.406: R23.2 29.01,24.16 | 32.47,21.46 33.74,21.46 34,21.71 R24.1
N$22
  Top 0.254: R37.2 34.25,9.43 | 33.24,12.06 C33.1 32.47,11.81 | 37.3,11.81 IC31.1 | C36.2 36.03,9.27 35.86,9.43
  Top 0.406: 34.25,9.43 35.86,9.43 | 32.47,11.81 34.51,11.81 | 34.51,11.81 37.3,11.81 | R37.2 34.51,9.27 34.51,11.81
N$23
  Top 0.254: C33.2 31.74,15.59 30.95,15.62 | 30.95,17.14 31.04,17.31 R35.2 | 29.43,15.11 29.51,15.02 R31.1
  Top 0.406: 30.95,17.14 30.95,16.12 30.95,15.62 30.19,15.62 29.43,15.11
N$24
  Top 0.254: 40.86,3.93 R39.1 41.11,4.44 | 41.11,6.47 41.07,6.47 R38.2 40.94,6.56 40.86,6.47 | IC31.6 43.65,8.76 42.63,7.74 | 43.05,7.49 42.89,7.49 42.63,7.74 | 42.63,7.74 C35.1
  Top 0.406: 41.11,4.44 41.11,6.47 | 42.89,7.49 41.62,7.49 40.94,6.56
N$25
  Top 0.254: R63.2 75.91,24 75.97,24.06 | 75.78,20.82 75.65,20.7 | R62.1 75.78,20.82 | 75.78,20.82 75.91,20.95
  Top 0.406: 75.97,24.06 IC61.4 | 75.91,20.95 R63.2
N$27
  Top 0.254: 67.53,14.6 67.79,14.61 IC51.17
  Top 0.406: JP51.7 67.53,20.7 67.53,14.6
N$30
  Top 0.254: 22.82,23.49 R41.1
  Top 0.406: JP41.3 21.04,25.78 21.3,25.52 21.3,24 21.81,23.49 22.82,23.49
N$33
  Top 0.254: 37.3,23.24 C22.2 | 37.3,25.27 R22.2 | IC31.14 37.3,16.89
  Top 0.406: 37.3,25.27 37.3,23.24 IC31.14
N$34  (via drill 0.61)
  Top 0.254: R43.2 19.77,19.93 20.37,19.34 | R44.1 52.03,22.98
  Top 0.406: 20.37,19.34 v22.07,19.34 R42.1 | v51.27,25.01 52.03,24 R44.1
  Bottom 0.61: v51.27,25.01 50,23.49 26.12,23.49 22.06,19.43 22.07,19.42 v22.07,19.34
N$38
  Top 0.254: C63.1 80.23,26.28 | 83.7,26.28 D61.C | IC61.1 81.24,24.18
  Top 0.406: 81.24,26.28 C63.1 | 81.24,26.28 83.7,26.28 | 81.24,24.18 81.24,26.28
N$39
  Top 0.254: LED61.A 14.19,2.41
  Top 0.406: LED61.A R61.1
N$40
  Top 0.406: 9V.1 D61.A
N$41
  Top 0.254: IC31.13 38.57,16.12 | IC31.13 38.57,17.9 | R21.1 35.27,17.39 35.78,17.39 36.54,17.39 36.54,15.36 38.57,15.36 IC31.13
  Top 0.406: 35.78,17.39 C21.2
N$42
  Top 0.254: 69.3,16.12 IC51.16
  Top 0.406: JP51.9 68.54,18.28 69.3,17.65 69.3,16.12
N$43  (via drill 0.61)
  Top 0.254: 70.1,18.38 IC51.15
  Top 0.406: v69.56,20.44 69.56,18.92 70.1,18.38
  Bottom 0.406: JP51.1 59.65,23.74 61.68,23.74 62.19,23.24 62.19,21.2
  Bottom 0.61: v69.56,20.44 62.95,20.44 62.19,21.2
N$45
  Top 0.254: IC31.8 44.92,16.89 44.86,16.95 | R21.2 35.36,15.02 35.78,14.6
  Top 0.406: 44.86,16.95 IC31.9 43.65,15.36 43.31,15.02 41.28,15.02 40.86,14.6 35.78,14.6
N$48
  Top 0.254: R43.1 18.25,19.93 18.5,20.19 18,20.19
  Top 0.406: 18,20.19 18,21.71 JP41.1
N$53  (via drill 0.61)
  Top 0.254: R31.2 27.81,15.2 | C31.1 51.29,13.05 50.76,13.58 | 47.97,19.43 R32.1
  Top 0.406: 27.81,15.2 26.89,15.87 v26.89,16.63 | v46.19,17.65 46.19,18.92 46.7,19.43 47.97,19.43 48.98,19.43 49.24,19.17 49.24,18.41 50.76,16.89 50.76,13.58
  Bottom 0.61: v26.89,16.63 45.17,16.63 v46.19,17.65
N$54
  Top 0.254: C34.2 47.97,15.62 46.95,15.62
  Top 0.406: IC31.5 42.38,13.58 42.89,14.09 45.43,14.09 46.95,15.62 | C34.2 R32.2
PWM  (via drill 0.61)
  Top 0.254: IC51.13 71.82,16.1 71.84,16.12 71.59,16.38
  Top 0.406: v71.08,17.65 71.59,17.14 71.59,16.38 | v52.03,14.85 R45.2
  Bottom 0.254: v52.03,14.85 52.01,14.83 52.06,14.83 v52.03,14.85
  Bottom 0.61: v52.03,14.85 52.03,16.89 52.79,17.65 v71.08,17.65
RLEG
  Top 0.254: C22.1 35.78,23.24 35.84,23.3 | C21.1 35.78,20.44 35.66,20.55 | R22.1 36.03,25.27 35.36,24.59
  Top 0.406: R22.1 35.84,23.3 | C22.1 35.66,20.55 | R24.2 35.36,24.59
RX
  Top 0.406: RX.1 74.64,3.17 73.3,4.51 IC51.30
TX
  Top 0.254: TX.1 78.19,3.17
  Top 0.406: IC51.31 74.1,5.74 74.64,5.2 76.16,5.2 78.19,3.17
VFB
  Top 0.254: 58.13,12.31 59.91,10.54 | R57.2 55.93,11.39 | R55.1 55.75,14.43 55.84,14.35 55.72,14.22
  Top 0.406: 59.91,10.54 IC52.R | 58.13,12.31 56.86,12.31 55.93,11.39 | R57.2 55.72,14.22
VGND  (via drill 0.61)
  Top 0.254: Q11.2 5.02,5.84 5.04,5.84 5.04,10.81 Q12.E 4.96,10.87 | Q13.2 3.52,3.53 | Q13.2 3.77,3.65 3.52,3.42 | Q14.E 3.52,8.61 3.52,5.46 | 3.52,3.42 3.52,5.46 | 5.04,21.2 C11.2 4.28,21.2 C13.1 | 3.52,5.46 3.63,5.35 | C15.2 8.74,6.11 | 8.09,5.46 8.09,3.68 6.82,2.41 4.53,2.41 4.53,3.42 | 3.52,3.42 3.58,3.62 Q13.2 | IC11.10 23.08,6.22 | 25.73,6.22 C14.2 25.88,6.09 | VR31.3 27.65,2.92 | 26.95,6.03 26.89,6.09 | 39.33,6.51 R38.1 39.24,6.64 39.47,6.87 | 23.84,20.95 23.93,21.04 R42.2 24.09,20.95 24.43,21.29 | 9.47,18.3 C41.1 9.61,18.41 10.12,18.41 10.38,18.66 10.38,18.92 10.63,19.17 15.2,19.17 | R35.1 29.34,17.48 | 46.7,10.03 47.71,10.03 | 47.71,10.03 47.97,10.03 | 54.57,4.95 IC41.6 | v42.13,1.9 41.87,1.65 | C45.1 53.42,6.11 53.3,6.22 | 38.82,19.43 C38.1 39.08,19.43 38.82,19.68 | C46.+ 40.09,24.51 39.59,24 39.59,23.74 | 29.43,21.46 C24.2 29.43,21.71 | C23.2 31.71,24 | 47.71,10.03 47.71,9.77 47.86,9.92 C34.1
  Top 0.406: 4.28,11.81 v4.28,19.43 4.28,21.2 4.28,22.98 v3.52,23.74 | 25.73,6.22 IC11.10 | 26.89,6.09 25.88,6.09 | 27.08,5.9 27.65,5.33 27.65,2.92 | 27.08,5.9 26.95,6.03 | VR31.2 VR31.3 27.9,1.65 28.16,1.39 39.08,1.39 39.33,1.65 | 39.33,1.65 39.33,6.51 | v26.38,19.17 25.62,19.17 25.62,20.7 25.36,20.95 24.09,20.95 | v26.38,19.17 27.65,19.17 | v46.7,8 46.7,10.03 | IC41.6 57.11,4.95 58.38,3.68 IC41.2 | v53.3,7.49 53.3,6.22 54.57,4.95 | 9.47,18.3 9.47,15.73 v8.85,15.11 | 41.87,1.65 39.33,1.65 | 39.33,1.65 39.33,2.92 v37.81,2.92 | 39.47,6.87 C37.2 | v25.36,14.85 24.6,14.09 24.6,10.54 25.11,10.03 29.43,10.03 R33.1 29.43,9.52 28.92,9.01 28.92,7.74 27.08,5.9 | 15.2,19.17 v16.22,20.19 | IC31.12 39.84,18.41 38.82,19.43 | 38.82,22.98 v38.82,20.95 38.82,19.68 | 23.84,20.95 22.57,20.95 v22.06,21.46 | v26.38,19.17 26.38,20.95 26.89,21.46 29.43,21.46 | 24.43,21.29 R41.2 | 3.52,3.42 4.53,3.42
  Bottom 0.254: 53.56,7.74 v53.3,7.49 52.79,8
  Bottom 0.61: v4.28,19.43 v8.09,19.43 | v16.22,20.19 20.79,20.19 v22.06,21.46 | v26.38,19.17 35.01,19.17 36.79,20.95 v38.82,20.95 v43.9,20.95 45.43,19.43 48.98,19.43 | JP51.3 58.64,20.44 48.98,20.44 48.98,19.43 | v42.13,1.9 54.32,1.9 54.83,2.41 54.83,7.74 | 48.98,19.43 48.98,15.11 52.54,11.55 53.81,11.55 54.83,10.54 54.83,7.74 | 54.83,7.74 53.56,7.74 | 52.79,8 v46.7,8
  other vias: 1.99,25.78 1.74,1.65 4.53,7.23 33.49,4.95
  pour Top (isolate 0.406): 0.47,-1.91 53.05,-1.91 53.05,32.63 0.47,32.63
  pour Bottom (isolate 0.406): 0.47,-1.91 53.05,-1.91 53.05,32.63 0.47,32.63

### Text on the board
Top: topside
Bottom: smt V1.11 | modEEG
Dimension: 28mm | 88mm
tPlace: 4 | 3 | 2 | 2 | 1 | 1 | C | A | R
tNames: SJ52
